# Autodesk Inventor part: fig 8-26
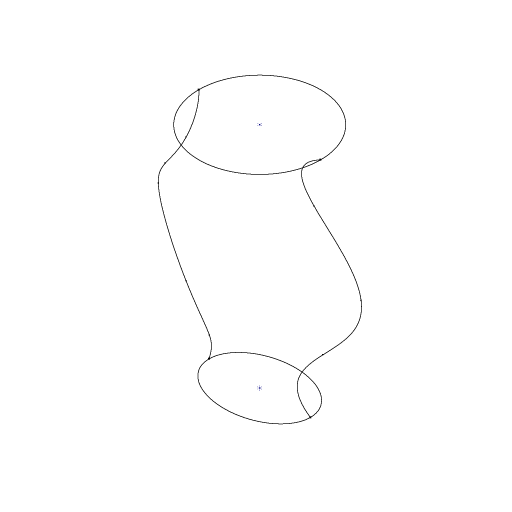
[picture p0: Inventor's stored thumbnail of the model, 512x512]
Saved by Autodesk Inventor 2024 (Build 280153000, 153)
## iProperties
Shininess: 64.0
Length Units: 11269
Angle Units: 11279
Time Units: 11290
Mass Units: 11283
Length Display Precision: 3
Angle Display Precision: 2
Compacted: True
Part Number: fig 8-26
Document SubType Name: Modeling
Created: 2002-12
Designer: deepak
Density: 1 g/cm^3
Material: Generic
Appearance: Default
Density: 0.0
Volumn: 0.0
Area: 0.0
PropertySet Name: Model Information
Control State: 0
Master: False
Checked Out: False
Author: deepak
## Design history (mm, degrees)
sketch "Sketch1"
  geometry: 2 further points; 1 other entity
  constraints: 1 coincident, 3 other
workplane "Work Plane1"
workplane "Work Plane2"
sketch "Sketch3"
  geometry: C1 r 60 at (0, 0); 1 further point
  constraints: 1 centre point, 1 coincident, 1 other
sketch "Sketch4"
  geometry: 8 further points
  constraints: 8 other
sketch "Sketch5"
  geometry: 6 further points
  constraints: 6 other
sketch "Sketch6"
  geometry: 6 further points
  constraints: 6 other
  dimensions: "d20" = 35 distance of point (0, 0) point (-35, 0); "d21" = 0 vertical distance of point (0, 0) point (-35, 0); "d22" = 225 vertical distance of point (0, 0) point (-60, 225); "d23" = 60 horizontal distance of point (0, 0) point (-60, 225); "d24" = 100 horizontal distance of point (0, 0) point (-100, 125); "d25" = 125 vertical distance of point (0, 0) point (-100, 125)
other parameters: "d5" = 125
